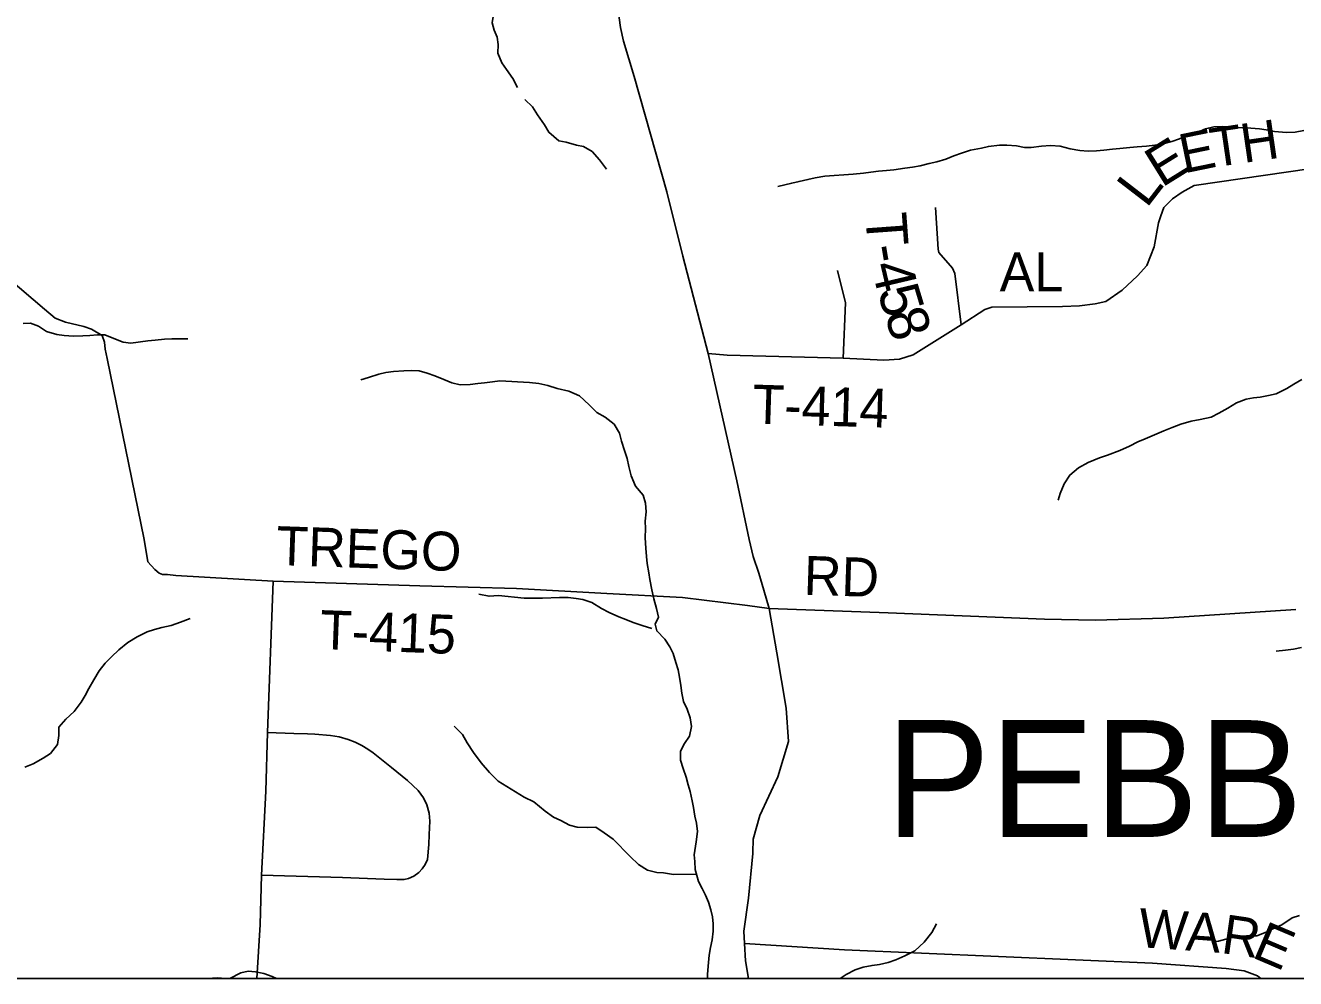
# Model space of a CAD drawing. Extents: x -139 to 835, y 0 to 440.
# Drawn here: x 183.8 to 242.7, y 185.4 to 229.6 of the extents above; entities that cross this region are included whole.
import ezdxf

# ---------------------------------------------------------------- set-up
doc = ezdxf.new("R2010")
doc.units = 0
for name, color, linetype in [('GM_X_County_Road', 7, 'Continuous'), ('GM_X_County_Text', 7, 'Continuous'), ('GM_X_Minor_Lake', 7, 'Continuous'), ('GM_X_Minor_River', 7, 'Continuous'), ('GM_X_State_Route', 7, 'Continuous'), ('GM_X_Township_Road', 7, 'Continuous'), ('GM_X_Township_Road_Text', 7, 'Continuous'), ('GM_X_Township_Text', 7, 'Continuous'), ('SH_Cut_Line', 7, 'Continuous')]:
    doc.layers.add(name, color=color, linetype=linetype)

msp = doc.modelspace()

# ---------------------------------------------------------------- linework, layer by layer
at = {"layer": 'GM_X_County_Road'}
msp.add_lwpolyline([(194.511, 185.387), (194.662, 187.889), (194.733, 190.189), (194.931, 194.081), (195.006, 196.798), (195.268, 203.828), (190.756, 204.082), (190.364, 204.135), (190.136, 204.137), (189.984, 204.199), (189.784, 204.358), (189.458, 204.711), (189.293, 205.751), (187.563, 214.142), (187.479, 214.577), (187.445, 214.903), (187.335, 215.218), (186.844, 215.513), (186.49, 215.637), (185.631, 215.839), (185.164, 216.025), (184.662, 216.441), (182.98, 217.87)], dxfattribs=at)
at = {"layer": 'GM_X_County_Text'}
msp.add_lwpolyline([(138.399, 185.387), (295.458, 185.387)], dxfattribs=at)
at = {"layer": 'GM_X_Minor_Lake'}
msp.add_lwpolyline([(192.961, 185.387), (192.875, 185.402), (192.697, 185.415), (192.456, 185.404), (192.395, 185.387)], dxfattribs=at)
at = {"layer": 'GM_X_Minor_River'}
for points in [[(206.506, 234.617), (206.29, 234.086), (206.074, 233.626), (205.985, 233.324), (206.01, 232.889), (206.111, 232.527), (206.06, 232.177), (205.92, 231.862), (205.678, 231.427), (205.5, 231.065), (205.5, 230.727), (205.538, 230.328), (205.474, 230.014), (205.423, 229.712), (205.512, 229.374), (205.652, 229.059), (205.702, 228.709), (205.689, 228.31), (205.88, 227.863), (206.083, 227.549), (206.388, 227.138), (206.604, 226.715)], [(206.936, 226.165), (207.295, 225.818), (207.528, 225.447), (207.85, 224.991), (208.057, 224.643), (208.519, 224.249), (208.863, 224.18), (209.335, 224.039), (209.666, 223.982), (210.063, 223.744), (210.398, 223.361), (210.72, 222.93)], [(243.067, 224.721), (242.66, 224.645), (242.253, 224.629), (241.705, 224.684), (241.323, 224.753), (241.004, 224.799), (240.609, 224.831), (240.215, 224.852), (239.769, 224.884), (239.311, 224.904), (238.891, 224.9), (238.497, 224.8), (238.117, 224.628), (237.673, 224.491), (237.305, 224.343), (236.95, 224.219), (236.582, 224.119), (236.15, 224.043), (235.768, 224.003), (235.336, 223.963), (234.992, 223.936), (234.535, 223.895), (234.191, 223.856), (233.785, 223.816), (233.454, 223.777), (233.06, 223.773), (232.678, 223.794), (232.231, 223.874), (231.76, 223.991), (231.314, 224.035), (230.894, 223.995), (230.424, 223.942), (230.106, 223.939), (229.736, 224.008), (229.29, 224.04), (228.946, 224.049), (228.438, 223.984), (228.12, 223.909), (227.612, 223.808), (227.181, 223.671), (226.826, 223.547), (226.458, 223.399), (226.039, 223.275), (225.696, 223.199), (225.265, 223.087), (224.909, 223.023), (224.566, 222.984), (224.045, 222.895), (223.714, 222.868), (223.332, 222.84), (222.977, 222.788), (222.646, 222.749), (222.163, 222.697), (221.73, 222.668), (221.285, 222.64), (220.853, 222.6), (220.396, 222.524), (220.065, 222.448), (219.659, 222.36), (219.316, 222.285), (218.999, 222.209), (218.668, 222.134)], [(183.68, 215.772), (184.011, 215.784), (184.392, 215.651), (184.761, 215.397), (185.231, 215.264), (185.574, 215.216), (186.006, 215.191), (186.438, 215.203), (186.769, 215.216), (187.125, 215.24), (187.468, 215.24), (187.887, 215.07), (188.319, 214.901), (188.675, 214.865), (189.463, 214.961), (189.794, 214.998), (190.226, 215.046), (190.569, 215.058), (191.306, 215.058)], [(199.326, 213.16), (199.694, 213.268), (200.165, 213.425), (200.495, 213.498), (200.851, 213.546), (201.321, 213.582), (201.677, 213.594), (202.033, 213.57), (202.414, 213.473), (202.758, 213.352), (203.19, 213.171), (203.558, 213.026), (203.939, 212.929), (204.397, 212.941), (204.753, 212.99), (205.071, 213.026), (205.439, 213.074), (205.783, 213.11), (207.158, 213.029)], [(207.158, 213.029), (207.591, 212.984), (208.012, 212.892), (208.446, 212.763), (208.982, 212.635), (209.467, 212.422), (209.917, 211.992), (210.276, 211.646), (210.66, 211.432), (211.083, 211.098), (211.329, 210.678), (211.421, 210.317), (211.565, 209.884), (211.683, 209.511), (211.763, 209.138), (211.869, 208.704), (212.064, 208.223), (212.424, 207.804), (212.53, 207.432), (212.559, 207.034), (212.524, 206.611), (212.528, 206.261), (212.519, 205.827), (212.549, 205.344), (212.578, 204.971), (212.619, 204.645), (212.687, 204.2), (212.728, 203.898), (212.821, 203.417), (212.914, 202.995), (213.045, 202.55), (213.138, 202.153), (212.976, 201.826), (213.055, 201.513), (213.428, 201.13), (213.66, 200.782), (213.815, 200.458), (213.946, 200.049), (214.051, 199.712), (214.118, 199.363), (214.173, 198.977), (214.227, 198.628), (214.294, 198.242), (214.463, 197.882), (214.606, 197.485), (214.674, 197.076), (214.576, 196.628), (214.337, 196.288), (214.15, 195.937), (214.154, 195.514), (214.284, 195.13), (214.415, 194.733), (214.508, 194.372), (214.6, 194.059), (214.705, 193.637), (214.759, 193.324), (214.827, 192.927), (214.893, 192.589), (214.948, 192.204), (214.886, 191.732), (214.791, 191.131)], [(242.969, 213.174), (242.602, 212.954), (242.273, 212.758), (241.779, 212.512), (241.423, 212.436), (241.042, 212.361), (240.724, 212.321), (240.394, 212.258), (239.938, 212.097), (239.545, 211.852), (239.115, 211.619), (238.76, 211.423), (238.252, 211.322), (237.846, 211.246), (237.363, 211.096), (236.957, 210.948), (236.577, 210.788), (236.133, 210.615), (235.702, 210.43), (235.373, 210.282), (234.98, 210.085), (234.536, 209.888), (233.966, 209.666), (233.585, 209.542), (233.065, 209.332), (232.609, 209.074), (232.205, 208.745), (231.942, 208.332), (231.768, 207.884), (231.669, 207.582)], [(204.798, 203.215), (205.281, 203.118), (205.713, 203.154), (206.907, 203.037)], [(206.907, 203.037), (207.352, 203.029), (207.759, 203.033), (208.548, 203.064), (208.956, 203.056), (209.312, 203.023), (209.631, 202.977), (210.052, 202.824), (210.487, 202.551), (210.845, 202.373), (211.293, 202.172), (211.625, 202.042), (211.957, 201.901), (212.378, 201.772), (212.825, 201.631)], [(191.413, 202.093), (190.968, 201.912), (190.536, 201.767), (190.104, 201.67), (189.761, 201.574), (189.43, 201.465), (188.96, 201.236), (188.528, 200.97), (188.108, 200.632), (187.765, 200.318), (187.485, 200.015), (187.205, 199.665), (186.95, 199.242), (186.721, 198.844), (186.543, 198.517), (186.365, 198.203), (186.034, 197.78), (185.653, 197.418), (185.335, 197.056), (185.322, 196.657), (185.271, 196.246), (184.94, 195.823), (184.61, 195.606), (184.139, 195.352), (183.745, 195.195)], [(242.956, 200.748), (242.588, 200.672), (242.207, 200.62), (241.787, 200.568)], [(203.664, 197.101), (204.045, 196.702), (204.26, 196.316), (204.553, 195.869), (204.921, 195.397), (205.302, 194.95), (205.708, 194.539), (206.915, 193.808)], [(206.915, 193.808), (207.35, 193.582), (207.876, 193.153), (208.273, 192.867), (208.605, 192.725), (209.014, 192.5), (209.359, 192.406), (209.83, 192.399), (210.224, 192.414), (210.621, 192.14), (211.031, 191.854), (211.83, 191.056)], [(214.894, 190.223), (213.829, 190.222), (213.371, 190.292), (213.053, 190.314), (212.634, 190.409), (212.213, 190.684), (211.83, 191.056)], [(215.416, 185.387), (215.415, 185.573), (215.438, 185.971), (215.487, 186.478), (215.549, 186.828), (215.623, 187.19), (215.672, 187.589), (215.671, 187.926), (215.644, 188.252), (215.566, 188.577), (215.462, 188.927), (215.321, 189.252), (215.167, 189.565), (214.988, 189.89), (214.832, 190.444), (214.818, 190.818), (214.791, 191.131)], [(221.567, 185.387), (221.847, 185.58), (222.252, 185.787), (222.633, 185.922), (223.039, 185.996), (223.382, 186.046), (223.789, 186.132), (224.144, 186.255), (224.563, 186.438), (225.032, 186.681), (225.462, 187.07), (225.816, 187.518), (226.03, 187.929)], [(242.87, 188.313), (242.528, 188.203), (242.046, 187.887), (241.716, 187.74), (241.31, 187.545), (240.879, 187.374), (240.409, 187.372), (239.951, 187.358), (239.443, 187.223), (239.113, 187.124), (238.796, 187.075)], [(193.265, 185.387), (193.776, 185.653), (194.106, 185.724), (194.449, 185.699), (194.829, 185.625), (195.222, 185.491), (195.429, 185.387)]]:
    msp.add_lwpolyline(points, dxfattribs=at)
at = {"layer": 'GM_X_State_Route'}
msp.add_lwpolyline([(217.304, 185.387), (217.178, 186.213), (217.13, 187.02), (217.1, 187.591), (217.304, 189.112), (217.506, 191.192), (217.506, 191.242), (217.532, 191.853), (217.83, 192.957), (218.669, 194.748), (219.172, 196.39), (219.062, 197.928), (218.623, 200.499), (218.271, 202.549), (218.027, 203.401), (217.794, 204.191), (217.535, 204.971), (217.339, 205.748), (216.777, 208.468), (215.448, 214.382), (214.272, 218.892), (213.525, 221.882), (212.015, 227.221), (211.512, 228.864), (211.376, 229.495), (211.239, 230.513)], dxfattribs=at)
at = {"layer": 'GM_X_Township_Road'}
for points in [[(236.86, 221.44), (236.97, 221.554), (237.416, 221.866), (237.977, 222.178), (245.559, 223.266), (246.667, 223.577), (249.674, 225.293), (250.005, 225.618), (250.324, 225.87), (250.617, 226.086), (251.317, 226.265), (252.501, 226.503), (253.519, 226.886), (254.729, 227.353), (255.684, 227.676), (256.384, 227.867), (257.071, 227.877), (260.922, 227.408), (264.957, 224.718)], [(215.448, 214.382), (216.319, 214.303), (221.706, 214.165), (223.58, 214.065), (224.318, 214.111), (224.941, 214.326), (227.173, 215.706), (228.267, 216.428), (228.598, 216.535), (231.879, 216.562), (232.668, 216.584), (233.38, 216.679), (233.877, 216.798), (234.641, 217.314), (235.356, 217.988), (235.79, 218.469), (236.123, 219.324), (236.33, 220.446), (236.433, 220.759), (236.574, 221.145), (236.86, 221.44)], [(227.173, 215.706), (226.872, 218.092), (226.765, 218.338), (226.14, 219.06), (226.11, 219.219), (225.988, 221.148)], [(221.706, 214.165), (221.813, 216.727), (221.432, 218.229)], [(195.268, 203.828), (202.071, 203.597), (206.552, 203.474), (210.749, 203.254), (214.251, 203.059), (217.264, 202.692), (218.271, 202.549), (223.795, 202.351), (231.03, 202.065), (233.395, 202.01), (236.574, 202.109), (242.692, 202.514)], [(194.733, 190.189), (198.487, 190.069), (200.41, 189.995), (201.01, 189.984), (201.343, 189.984), (201.543, 190.037), (201.788, 190.132), (202.021, 190.311), (202.177, 190.48), (202.321, 190.68), (202.421, 190.912), (202.488, 191.608), (202.499, 192.072), (202.533, 192.694), (202.51, 193.053), (202.388, 193.443), (202.232, 193.77), (201.988, 194.108), (201.499, 194.572), (200.751, 195.178), (199.912, 195.852), (199.654, 196.036), (199.374, 196.206), (199.073, 196.349), (198.75, 196.478), (198.334, 196.594), (197.932, 196.662), (197.208, 196.723), (196.857, 196.737), (196.226, 196.757), (195.006, 196.798)], [(241.071, 185.387), (240.91, 185.521), (240.302, 185.746), (239.462, 185.853), (236.052, 186.1), (221.757, 186.722), (217.13, 187.02)]]:
    msp.add_lwpolyline(points, dxfattribs=at)
at = {"layer": 'SH_Cut_Line'}
msp.add_lwpolyline([(67.578, 336.518), (67.578, 185.387), (295.458, 185.387), (295.458, 319.381), (267.909, 321.538), (228.151, 324.569), (207.436, 326.102), (194.287, 327.176), (177.155, 328.576), (171.559, 329.033), (160.688, 329.921), (158.444, 330.1), (105.67, 333.828), (92.493, 334.759)], close=True, dxfattribs=at)

# ---------------------------------------------------------------- texts
at = {"layer": 'GM_X_Township_Road_Text'}
for s, height, rotation, p in [('H', 1.809, 8.23891, (240.267, 223.215)), ('E', 1.813, 11.61489, (237.498, 222.729)), ('T', 1.81, 8.3256, (238.86, 223.009)), ('E', 1.85, 31.81406, (236.475, 222.056)), ('L', 1.886, 52.39739, (235.766, 221.083)), ('T', 1.904, 274.16915, (222.725, 220.846)), ('-', 1.903, 279.6301, (222.845, 219.322)), ('4', 1.903, 283.2818, (222.993, 218.472)), ('AL', 1.8056, 0.00001, (228.957, 217.261)), ('5', 1.902, 286.73674, (223.278, 217.277)), ('8', 1.901, 287.67004, (223.609, 216.178)), ('T-414', 1.8058, 358.17488, (217.47, 211.137)), ('TREGO', 1.8059, 358.04663, (195.388, 204.572)), ('RD', 1.8058, 358.12634, (219.851, 203.194)), ('T-415', 1.8059, 357.87042, (197.41, 200.677)), ('W', 1.807, 355.99456, (235.351, 186.853)), ('A', 1.807, 355.82891, (237.55, 186.699)), ('R', 1.809, 351.76774, (239.183, 186.582)), ('E', 1.832, 336.99539, (240.599, 186.394))]:
    msp.add_text(s, height=height, rotation=rotation, dxfattribs=at).set_placement(p)
at = {"layer": 'GM_X_Township_Text'}
msp.add_text('PEBBLE', height=5.4169, rotation=0.00001, dxfattribs=at).set_placement((223.679, 191.958))

doc.saveas('drawing.dxf')
